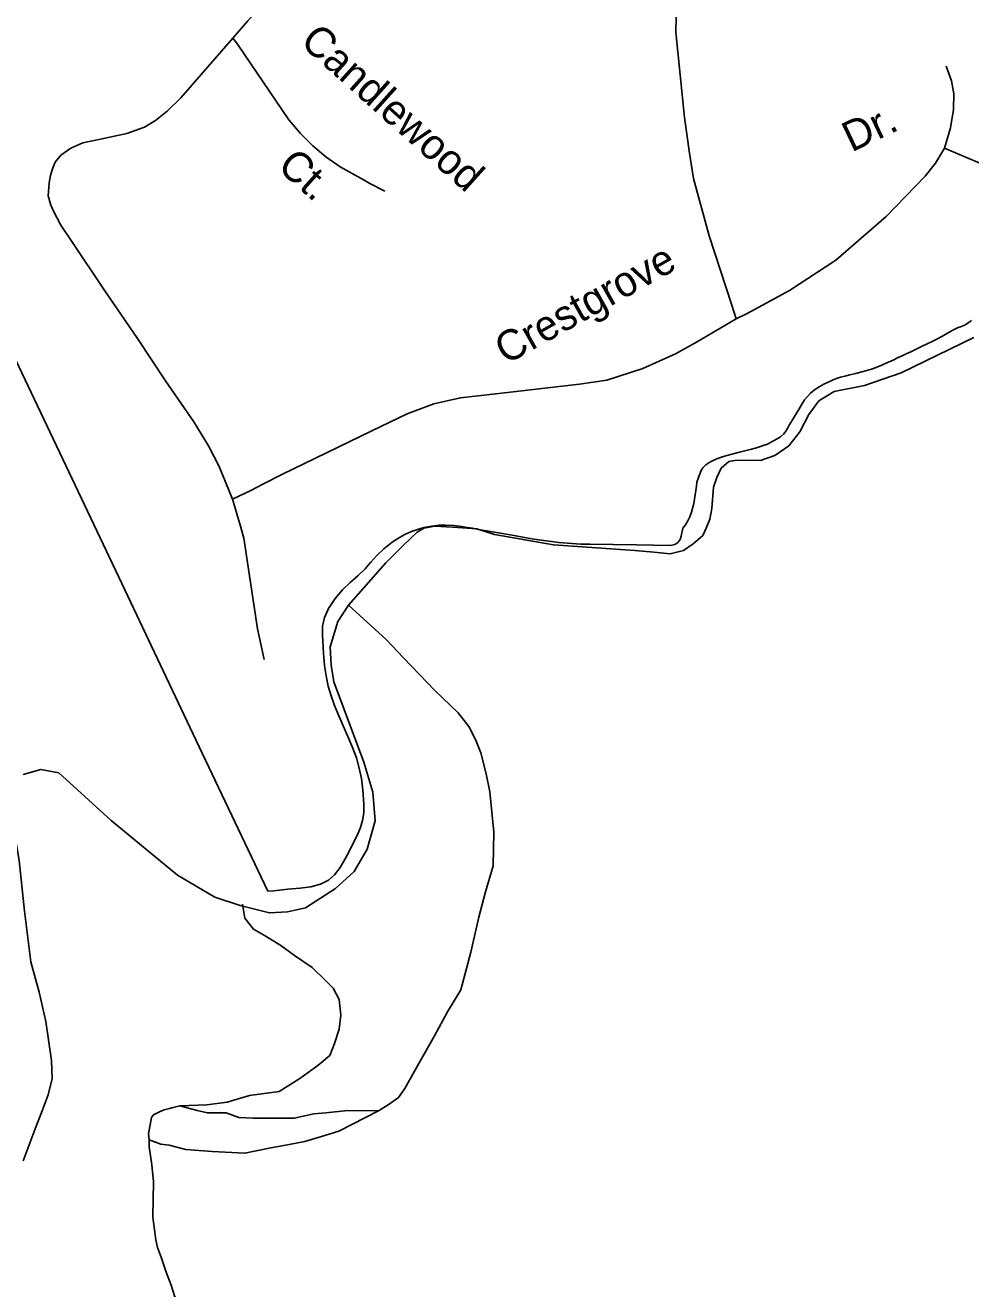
# Model space of a CAD drawing. Extents: x 884530 to 1028605, y 526725 to 653634.
# Drawn here: x 964663 to 966712, y 559825 to 562564 of the extents above; entities that cross this region are included whole.
import ezdxf

# ---------------------------------------------------------------- set-up
doc = ezdxf.new("R2010")
doc.units = 0
for name, color, linetype in [('Exist Boundary Political City Limit New', 7, 'Continuous'), ('Exist Road Non-System Type 51', 7, 'Continuous'), ('Exist Road Non-System Type 51 Label', 7, 'Continuous'), ('Exist Road Secondary Type 51 Attributed', 7, 'Continuous'), ('Map Preparation Boundary City Limit Buffer Line', 7, 'Continuous')]:
    doc.layers.add(name, color=color, linetype=linetype)

msp = doc.modelspace()

# ---------------------------------------------------------------- linework, layer by layer
at = {"layer": 'Exist Boundary Political City Limit New'}
for points in [[(966146.6, 561616.3), (966155.8, 561621.1), (966165.4, 561625.2), (966176.2, 561629), (966186.4, 561631.8), (966197.5, 561634.6), (966210.9, 561637.9), (966225.3, 561641.7), (966237.4, 561644.9), (966248.1, 561647.9), (966258.6, 561651.1), (966264.9, 561653.3), (966271.5, 561655.9), (966278.2, 561658.9), (966285.2, 561662.6), (966293.1, 561667.1), (966300, 561671.8), (966306.3, 561677.2), (966312.1, 561684.5), (966314.1, 561687.7), (966315.9, 561690.8), (966317.4, 561693.6), (966318.9, 561696.5), (966320, 561698.8), (966336.4, 561725.3), (966351.9, 561751.9), (966357.8, 561758.5), (966365.4, 561766.3), (966373.7, 561773.2), (966383.8, 561779.8), (966393.9, 561785.5), (966403.4, 561790.3), (966412.6, 561794.4), (966421.4, 561797.8), (966430.4, 561800.6), (966439.8, 561803), (966450.6, 561805.7), (966463.3, 561809.1), (966476.4, 561812.5), (966487.1, 561815.3), (966496.9, 561818.1), (966507.2, 561821.7), (966519.8, 561826.8), (966532.1, 561832.4), (966539.1, 561835.7), (966543.9, 561838), (966555, 561843.3), (966563.6, 561847.4), (966572.3, 561851.5), (966582.2, 561856.1), (966593.9, 561861.8), (966606.9, 561867.9), (966617.7, 561872.8), (966627.4, 561877.4), (966637.5, 561882.6), (966649.6, 561889.2), (966661.8, 561896.2), (966673.7, 561902.8), (966685.2, 561908.2), (966692, 561911), (966698.8, 561913.9), (966706.1, 561917.8), (966714, 561923.6)], [(964629, 561866.5), (964865.9, 561367.1), (965046.9, 560985.9), (965189.1, 560686.4), (965202.1, 560687.4), (965232.1, 560690.6), (965241.3, 560691.4), (965258.9, 560693.1), (965282.5, 560696.2), (965303, 560701.5), (965320.4, 560710.1), (965333.6, 560721.9), (965345.7, 560738), (965356.9, 560756.8), (965367.3, 560776.6), (965383.8, 560810.6), (965389.8, 560824.8), (965394.3, 560839.8), (965396.9, 560856.5), (965397.2, 560876), (965395, 560905.5), (965391.8, 560930.8), (965387.1, 560953.5), (965380.8, 560975.5), (965372.4, 560998.3), (965364.8, 561017.1), (965340.9, 561071.6), (965333.6, 561089.4), (965326.2, 561110.1), (965320, 561131.2), (965315.1, 561153.2), (965312.6, 561170.7), (965311.6, 561176.6), (965309.7, 561201.8), (965307.2, 561242.5), (965307.8, 561261.1), (965311.7, 561279.8), (965320.4, 561299.3), (965335.1, 561321.2), (965350.9, 561339.6), (965367.4, 561355.6), (965383.8, 561370.5), (965399.6, 561385.6), (965407.2, 561393.9), (965412.4, 561399.6), (965424.9, 561414.4), (965440.2, 561428.9), (965458.1, 561443.2), (965474.1, 561453.4), (965485.8, 561459.6), (965500.4, 561466.1), (965511.4, 561470.1), (965527, 561474.6), (965544.4, 561478), (965560.1, 561479.8), (965574.1, 561480.2), (965591.5, 561479.6), (965604.3, 561478.1), (965616.5, 561476), (965632.2, 561473.2), (965645.9, 561470.9), (965679.9, 561464.9), (965722.8, 561457.4), (965745.3, 561453.6), (965765.4, 561450), (965793.1, 561445.7), (965819.5, 561442.5), (965867, 561438.8), (965886.7, 561438.7), (965987.9, 561437.1), (966061.7, 561436.2), (966070.2, 561437.9), (966073.6, 561439.4), (966078.5, 561443.4), (966082.9, 561448.8), (966084.8, 561456.3), (966088.1, 561473.4), (966094.1, 561480.6), (966099.4, 561489.1), (966103.8, 561498.4), (966107.4, 561507.9), (966112.2, 561527.2), (966115.2, 561546), (966118.3, 561564.2), (966118.6, 561573.1), (966122.2, 561583.1), (966125.1, 561591.4), (966128.1, 561598.4), (966132, 561604.4), (966138.4, 561610.7), (966146.6, 561616.3)]]:
    msp.add_lwpolyline(points, dxfattribs=at)
at = {"layer": 'Exist Road Non-System Type 51'}
msp.add_line((966655.8, 562297), (966863.2, 562208.4), dxfattribs=at)
for points in [[(966700.2, 563167), (966654.7, 563132.1), (966594.7, 563076.7), (966559.6, 563030.3), (966526.2, 562981.4), (966508.2, 562960.6), (966486.9, 562943.7), (966425.2, 562901.8), (966245.7, 562800.6), (966179.2, 562761.1), (966148.4, 562737.3), (966131.4, 562720.1), (966119.6, 562707.3), (966110.9, 562695.7), (966097.4, 562674.6), (966088.4, 562659.6), (966074.6, 562613.6), (966073.2, 562549), (966092.3, 562364.1), (966102.9, 562286.5), (966111.5, 562231.8), (966145.3, 562107.2), (966193.8, 561959.3), (966204.3, 561927.2)], [(965396.7, 562863.8), (965332.3, 562781.7), (965145.5, 562573.6), (965112.8, 562535.7)], [(965112.8, 562535.7), (965000.6, 562406.8), (964970.8, 562377.4), (964945.8, 562357.4), (964921.4, 562342.7), (964883.2, 562328.8), (964826.2, 562316.8), (964788.2, 562308.6), (964762.4, 562297.4), (964740.7, 562282.4), (964728.2, 562266.8), (964722, 562252.8), (964718, 562237.8), (964714.9, 562222), (964713, 562194.2), (964717.8, 562176), (964722.8, 562163.3), (964740.4, 562130.6), (964762.9, 562097), (964835.9, 561988.3), (964906.2, 561884.6), (964967.5, 561793.2), (965028.3, 561704.2), (965060.7, 561651.9), (965083.6, 561607.5), (965112.7, 561536.1)], [(965112.8, 562535.7), (965123, 562522.7), (965234.7, 562358.4), (965259.6, 562329), (965286.5, 562302.1), (965314.7, 562278.7), (965345.8, 562256.8), (965397.9, 562227.6), (965410.3, 562220.6), (965442.3, 562204)], [(966655.8, 562297), (966668.7, 562341.4), (966675.2, 562381.5), (966675.7, 562414.8), (966670.3, 562443.3), (966658.8, 562475.4)], [(966204.3, 561927.2), (966228.1, 561938.7), (966319.5, 561988.5), (966419.7, 562054.8), (966529.3, 562148.9), (966613.4, 562236.8), (966635.7, 562265.1), (966655.8, 562297)], [(965112.7, 561536.1), (965152.4, 561555), (965179.5, 561569.3), (965219, 561589.6), (965414.2, 561684.3), (965490.7, 561721.4), (965548.8, 561743.3), (965606.5, 561756.4), (965682.8, 561764.6), (965864.5, 561785.9), (965923.9, 561794.4), (966002, 561819.5), (966072.5, 561851.4), (966118.2, 561876.6), (966204.3, 561927.2)], [(965112.7, 561536.1), (965118.8, 561514.7), (965123.6, 561499.8), (965128.5, 561483.2), (965136.8, 561451.6), (965166.9, 561254.9), (965180.7, 561188.9)], [(965363.8, 561306.5), (965445.5, 561232), (965482.7, 561192.7), (965550.9, 561121.4), (965601.6, 561072.8), (965624.9, 561043.3), (965639.3, 561015.4), (965650.7, 560986.4), (965662.1, 560940.9), (965670.3, 560901.6), (965679.1, 560814.2), (965677.1, 560741.8), (965660.5, 560684.9), (965646, 560630.1), (965629, 560554.1), (965607.3, 560472.4), (965578.3, 560424.8), (965550.4, 560373.1), (965506.5, 560296), (965485.8, 560258.8), (965472.3, 560239.2), (965451.7, 560224.7), (965428.9, 560210.2)], [(964604.6, 560879.3), (964626.4, 560847), (964638.7, 560820.9), (964650.1, 560752.8), (964661.5, 560643.3), (964675.6, 560533), (964693.5, 560467.7), (964707.6, 560403.8), (964720.1, 560319.6), (964721.4, 560280.6), (964712.6, 560245.3), (964700, 560210.1), (964685, 560171.1), (964658.5, 560101.9)], [(965134, 560658.1), (965138.8, 560627.9), (965158.1, 560604.2), (965183.2, 560589.5), (965217.2, 560568.8), (965246.9, 560546.9), (965285.1, 560520.7), (965313.9, 560493.2), (965330.5, 560476.5), (965343.7, 560451.4), (965347.4, 560417.9), (965343.6, 560387.5), (965333.6, 560356.2), (965323.7, 560330.6), (965297, 560308.5), (965258.6, 560280.3), (965213.5, 560252), (965149.1, 560243.6), (965101.2, 560229.3), (965057.1, 560223.4), (964998.6, 560221)], [(964998.6, 560221), (964984.2, 560217.4), (964975.9, 560215), (964964, 560212.6), (964955.6, 560209), (964948.4, 560205.4), (964941.3, 560201.9), (964936.9, 560195.9), (964930.6, 560160.1), (964931.6, 560147.1)], [(965428.9, 560210.2), (965342.6, 560166.3), (965305.4, 560154.9), (965269.2, 560143.5), (965235, 560137.3), (965191.6, 560129), (965139.4, 560118.2), (965068.1, 560122.3), (965011.2, 560126.4), (964975, 560135.7), (964957.4, 560137.8), (964931.6, 560147.1)], [(965428.9, 560210.2), (965362.2, 560210.7), (965314.7, 560205.6), (965288.8, 560203.5), (965246.4, 560194.2), (965209.2, 560194.2), (965157.5, 560194.2), (965126.5, 560196.2), (965098.6, 560205.6), (965058.2, 560205.6), (965035.5, 560210.7), (964998.6, 560221)], [(964931.6, 560147.1), (964931.7, 560132.6), (964937.7, 560093.2), (964941.3, 560056.2), (964940.1, 559979.8), (964946.1, 559930.8), (964949.6, 559914.1), (964958.5, 559891), (964968.7, 559860.3), (964979.3, 559832.1), (964987, 559809), (964994.8, 559790.7), (965013.6, 559764.6), (965047.7, 559719.4), (965096.3, 559664.2), (965158.3, 559608.1), (965208.7, 559552.7), (965256.7, 559491), (965329.6, 559380.6), (965356.2, 559327.5), (965382.9, 559256.6), (965403.5, 559194.6)]]:
    msp.add_lwpolyline(points, dxfattribs=at)
at = {"layer": 'Exist Road Secondary Type 51 Attributed'}
for points in [[(966718.8, 561887.2), (966561.2, 561809.9), (966481.8, 561782.6), (966416.3, 561769.5), (966383.1, 561749.4), (966361.3, 561719.7), (966342.1, 561682.1), (966318.1, 561651.9), (966287.6, 561630.7), (966256.6, 561620.4), (966237, 561620.9), (966201.3, 561620.4), (966188.4, 561617.8), (966171.8, 561603.3), (966162.2, 561583.3), (966154.8, 561562.5), (966151.1, 561515.9), (966147, 561493.2), (966139.2, 561473.5), (966131.6, 561457.4), (966110.8, 561439.4), (966089.6, 561425.4), (966061.2, 561418.2)], [(966061.2, 561418.2), (966025.5, 561421.3), (965984.2, 561424.9), (965808, 561437.3), (965680, 561460), (965641.6, 561472.3), (965589.2, 561475.8), (965550.7, 561477.5), (965527.4, 561473.8), (965512.9, 561465), (965499, 561452.1), (965481.4, 561435), (965444.7, 561398.3), (965363.8, 561306.5), (965340.5, 561270.8), (965324, 561216), (965326, 561176.7), (965332.2, 561140.5), (965396.9, 560966.2), (965416.5, 560901.1), (965421.5, 560839), (965404, 560777.8), (965376, 560728.8), (965335.9, 560692.1), (965270.3, 560650.6), (965231.4, 560641.5), (965192.6, 560639.2), (965129.1, 560655.7), (965073.8, 560673.8), (964993.5, 560721), (964849.3, 560839.8), (964735.8, 560943), (964697.4, 560950), (964658.9, 560939.5)]]:
    msp.add_lwpolyline(points, dxfattribs=at)
at = {"layer": 'Map Preparation Boundary City Limit Buffer Line'}
for points in [[(966146.6, 561616.3), (966155.8, 561621.1), (966165.4, 561625.2), (966176.2, 561629), (966186.4, 561631.8), (966197.5, 561634.6), (966210.9, 561637.9), (966225.3, 561641.7), (966237.4, 561644.9), (966248.1, 561647.9), (966258.6, 561651.1), (966264.9, 561653.3), (966271.5, 561655.9), (966278.2, 561658.9), (966285.2, 561662.6), (966293.1, 561667.1), (966300, 561671.8), (966306.3, 561677.2), (966312.1, 561684.5), (966314.1, 561687.7), (966315.9, 561690.8), (966317.4, 561693.6), (966318.9, 561696.5), (966320, 561698.8), (966336.4, 561725.3), (966351.9, 561751.9), (966357.8, 561758.5), (966365.4, 561766.3), (966373.7, 561773.2), (966383.8, 561779.8), (966393.9, 561785.5), (966403.4, 561790.3), (966412.6, 561794.4), (966421.4, 561797.8), (966430.4, 561800.6), (966439.8, 561803), (966450.6, 561805.7), (966463.3, 561809.1), (966476.4, 561812.5), (966487.1, 561815.3), (966496.9, 561818.1), (966507.2, 561821.7), (966519.8, 561826.8), (966532.1, 561832.4), (966539.1, 561835.7), (966543.9, 561838), (966555, 561843.3), (966563.6, 561847.4), (966572.3, 561851.5), (966582.2, 561856.1), (966593.9, 561861.8), (966606.9, 561867.9), (966617.7, 561872.8), (966627.4, 561877.4), (966637.5, 561882.6), (966649.6, 561889.2), (966661.8, 561896.2), (966673.7, 561902.8), (966685.2, 561908.2), (966692, 561911), (966698.8, 561913.9), (966706.1, 561917.8), (966714, 561923.6)], [(964629, 561866.5), (964865.9, 561367.1), (965046.9, 560985.9), (965189.1, 560686.4), (965202.1, 560687.4), (965232.1, 560690.6), (965241.3, 560691.4), (965258.9, 560693.1), (965282.5, 560696.2), (965303, 560701.5), (965320.4, 560710.1), (965333.6, 560721.9), (965345.7, 560738), (965356.9, 560756.8), (965367.3, 560776.6), (965383.8, 560810.6), (965389.8, 560824.8), (965394.3, 560839.8), (965396.9, 560856.5), (965397.2, 560876), (965395, 560905.5), (965391.8, 560930.8), (965387.1, 560953.5), (965380.8, 560975.5), (965372.4, 560998.3), (965364.8, 561017.1), (965340.9, 561071.6), (965333.6, 561089.4), (965326.2, 561110.1), (965320, 561131.2), (965315.1, 561153.2), (965312.6, 561170.7), (965311.6, 561176.6), (965309.7, 561201.8), (965307.2, 561242.5), (965307.8, 561261.1), (965311.7, 561279.8), (965320.4, 561299.3), (965335.1, 561321.2), (965350.9, 561339.6), (965367.4, 561355.6), (965383.8, 561370.5), (965399.6, 561385.6), (965407.2, 561393.9), (965412.4, 561399.6), (965424.9, 561414.4), (965440.2, 561428.9), (965458.1, 561443.2), (965474.1, 561453.4), (965485.8, 561459.6), (965500.4, 561466.1), (965511.4, 561470.1), (965527, 561474.6), (965544.4, 561478), (965560.1, 561479.8), (965574.1, 561480.2), (965591.5, 561479.6), (965604.3, 561478.1), (965616.5, 561476), (965632.2, 561473.2), (965645.9, 561470.9), (965679.9, 561464.9), (965722.8, 561457.4), (965745.3, 561453.6), (965765.4, 561450), (965793.1, 561445.7), (965819.5, 561442.5), (965867, 561438.8), (965886.7, 561438.7), (965987.9, 561437.1), (966061.7, 561436.2), (966070.2, 561437.9), (966073.6, 561439.4), (966078.5, 561443.4), (966082.9, 561448.8), (966084.8, 561456.3), (966088.1, 561473.4), (966094.1, 561480.6), (966099.4, 561489.1), (966103.8, 561498.4), (966107.4, 561507.9), (966112.2, 561527.2), (966115.2, 561546), (966118.3, 561564.2), (966118.6, 561573.1), (966122.2, 561583.1), (966125.1, 561591.4), (966128.1, 561598.4), (966132, 561604.4), (966138.4, 561610.7), (966146.6, 561616.3)]]:
    msp.add_lwpolyline(points, dxfattribs=at)

# ---------------------------------------------------------------- texts
at = {"layer": 'Exist Road Non-System Type 51 Label'}
for s, rotation, p in [('Candlewood', 318.1561, (965256.4, 562524.1)), ('Dr.', 25.4455, (966454, 562287.8)), ('Ct.', 318.1561, (965207.1, 562253.7)), ('Crestgrove', 29.2692, (965704.8, 561827))]:
    msp.add_text(s, height=65.62, rotation=rotation, dxfattribs=at).set_placement(p)

doc.saveas('drawing.dxf')
